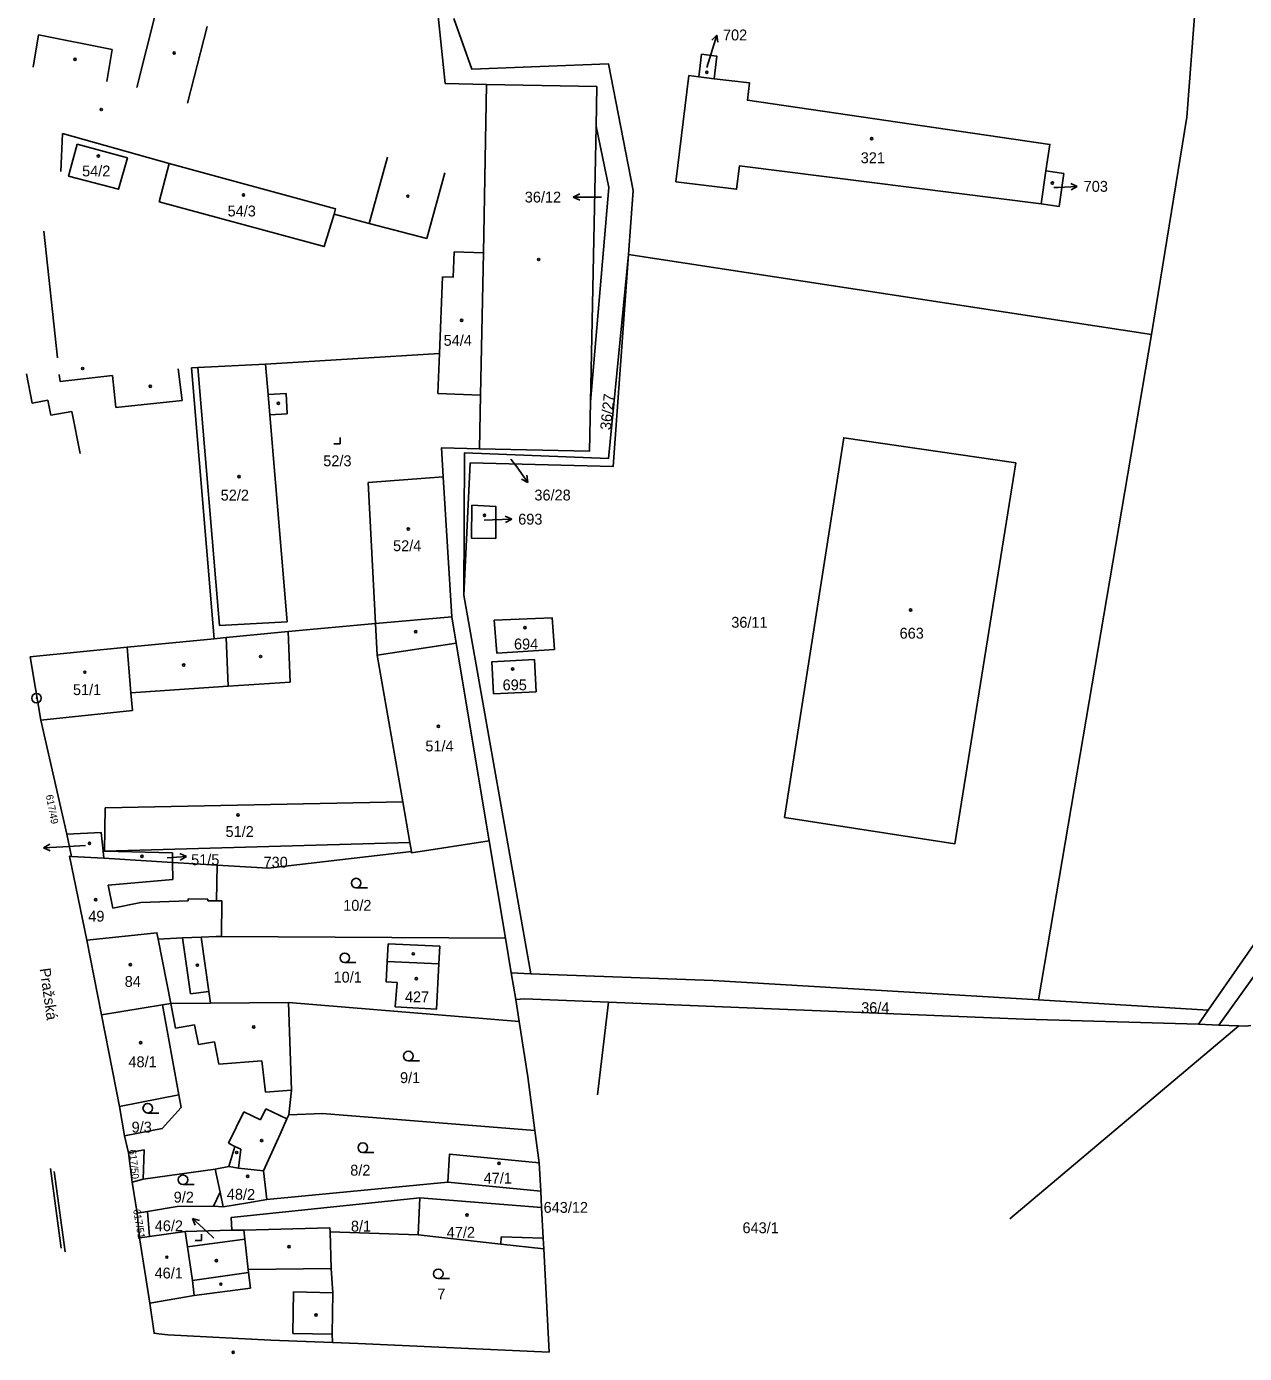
# Model space of a CAD drawing. Extents: x -783948 to -781889, y -1005870 to -1004430.
# Drawn here: x -782644.9 to -782454.1, y -1005869.8 to -1005661.9 of the extents above; entities that cross this region are included whole.
import ezdxf

# ---------------------------------------------------------------- set-up
doc = ezdxf.new("R2010")
doc.units = 0
for name, color, linetype in [('Vrstva 1', 7, 'Continuous'), ('Vrstva 2', 7, 'Continuous'), ('Vrstva 3', 7, 'Continuous'), ('Vrstva 4', 7, 'Continuous'), ('Vrstva 5', 7, 'Continuous'), ('Vrstva 7', 7, 'Continuous'), ('Vrstva 8', 7, 'Continuous')]:
    doc.layers.add(name, color=color, linetype=linetype)

msp = doc.modelspace()

# ---------------------------------------------------------------- linework, layer by layer
at = {"layer": 'Vrstva 1'}
for p, q in [((-782580.46, -1005660.33), (-782579.32, -1005670.89)), ((-782537.2, -1005670.12), (-782539.61, -1005669.83)), ((-782572.84, -1005671.02), (-782579.32, -1005670.89)), ((-782555.58, -1005671.36), (-782572.84, -1005671.02)), ((-782555.71, -1005677.54), (-782555.58, -1005671.36)), ((-782556.59, -1005720.71), (-782555.71, -1005677.54)), ((-782486, -1005689.74), (-782485.24, -1005684.56)), ((-782485.24, -1005684.56), (-782482.42, -1005684.99)), ((-782482.42, -1005684.99), (-782483.18, -1005690.13)), ((-782483.18, -1005690.13), (-782486, -1005689.74)), ((-782550.6, -1005697.65), (-782468.7, -1005710.19)), ((-782580.24, -1005713.13), (-782579.78, -1005701.14)), ((-782468.7, -1005710.19), (-782486.38, -1005814.37)), ((-782580.24, -1005713.13), (-782607.48, -1005714.81)), ((-782618.07, -1005715.37), (-782619.07, -1005715.42)), ((-782615.5, -1005757.82), (-782619.07, -1005715.42)), ((-782607.48, -1005714.81), (-782618.07, -1005715.37)), ((-782618.07, -1005715.37), (-782614.7, -1005755.73)), ((-782604.11, -1005722.61), (-782604.25, -1005719.42)), ((-782573.95, -1005728.07), (-782573.79, -1005719.66)), ((-782578.29, -1005754.37), (-782579.65, -1005732.46)), ((-782576.39, -1005750.98), (-782565.92, -1005810.3)), ((-782614.7, -1005755.73), (-782604.09, -1005755.19)), ((-782578.29, -1005754.37), (-782590.23, -1005755.45)), ((-782632.69, -1005791.09), (-782632.59, -1005784.29)), ((-782632.59, -1005784.29), (-782585.99, -1005783.36)), ((-782584.88, -1005789.75), (-782585.99, -1005783.36)), ((-782637.85, -1005791.91), (-782638.59, -1005788.42)), ((-782632.69, -1005791.09), (-782584.88, -1005789.75)), ((-782584.88, -1005789.75), (-782584.63, -1005791.16)), ((-782569.89, -1005804.73), (-782572.45, -1005789.49)), ((-782632.78, -1005792.21), (-782637.85, -1005791.91)), ((-782632.9, -1005791.09), (-782632.69, -1005791.09)), ((-782632.9, -1005791.09), (-782632.78, -1005792.21)), ((-782622.03, -1005792.86), (-782632.78, -1005792.21)), ((-782622.05, -1005791.33), (-782632.69, -1005791.09)), ((-782622.03, -1005792.86), (-782622.05, -1005791.33)), ((-782615.07, -1005793.28), (-782622.03, -1005792.86)), ((-782635.48, -1005805.01), (-782633.18, -1005816.7)), ((-782569.89, -1005804.73), (-782614.39, -1005804.47)), ((-782568.98, -1005810.16), (-782569.89, -1005804.73)), ((-782565.92, -1005810.3), (-782568.98, -1005810.16)), ((-782568.28, -1005814.33), (-782568.98, -1005810.16)), ((-782603.87, -1005814.79), (-782616.1, -1005814.88)), ((-782567.74, -1005817.79), (-782603.87, -1005814.79)), ((-782567.74, -1005817.79), (-782568.28, -1005814.33)), ((-782553.75, -1005814.74), (-782555.46, -1005829.27)), ((-782486.38, -1005814.37), (-782459.82, -1005815.99)), ((-782633.18, -1005816.7), (-782630.36, -1005831.08)), ((-782461.32, -1005818.2), (-782459.82, -1005815.99)), ((-782490.91, -1005848.68), (-782455.01, -1005818.44)), ((-782458.16, -1005818.32), (-782461.32, -1005818.2)), ((-782455.01, -1005818.44), (-782458.16, -1005818.32)), ((-782630.36, -1005831.08), (-782629.54, -1005835.68)), ((-782598.54, -1005832.18), (-782603.85, -1005832.37)), ((-782565.28, -1005834.82), (-782598.54, -1005832.18)), ((-782629.54, -1005835.68), (-782628.92, -1005838.35)), ((-782564.61, -1005839.9), (-782565.28, -1005834.82)), ((-782628.34, -1005842.92), (-782628.92, -1005838.35)), ((-782626.64, -1005842.48), (-782628.34, -1005842.92)), ((-782626.64, -1005842.48), (-782615.37, -1005840.91)), ((-782615.37, -1005840.91), (-782614.59, -1005844.5)), ((-782607.26, -1005845.66), (-782607.8, -1005841.15)), ((-782628.34, -1005842.92), (-782627.59, -1005847.8)), ((-782614.59, -1005844.5), (-782615.63, -1005846.67)), ((-782614.09, -1005846.78), (-782615.63, -1005846.67)), ((-782583.33, -1005845.38), (-782583.57, -1005851.18)), ((-782583.33, -1005845.38), (-782564.24, -1005846.87)), ((-782627.59, -1005847.8), (-782625.95, -1005847.52)), ((-782627.21, -1005851.66), (-782627.59, -1005847.8)), ((-782625.95, -1005847.52), (-782625.66, -1005851.44)), ((-782620.05, -1005850.63), (-782625.66, -1005851.44)), ((-782612.74, -1005850.46), (-782620.05, -1005850.63)), ((-782610.87, -1005850.42), (-782612.74, -1005850.46)), ((-782583.57, -1005851.18), (-782597.37, -1005850.7)), ((-782625.66, -1005851.44), (-782627.21, -1005851.66)), ((-782563.03, -1005869.55), (-782563.89, -1005853.39)), ((-782597, -1005868.03), (-782606.64, -1005867.68)), ((-782592.99, -1005868.18), (-782597, -1005868.03)), ((-782563.03, -1005869.55), (-782592.99, -1005868.18))]:
    msp.add_line(p, q, dxfattribs=at)
for points in [[(-782459.82, -1005815.99), (-782443.68, -1005792.79), (-782417.66, -1005746.96), (-782388.6, -1005683.51), (-782362.9, -1005633.05), (-782362.27, -1005590.2)], [(-782359.84, -1005633.71), (-782386.44, -1005686.23), (-782414.15, -1005746.16), (-782437.86, -1005788.34), (-782449.27, -1005805.98), (-782458.16, -1005818.32)], [(-782461.42, -1005652.75), (-782463.16, -1005676.14), (-782468.7, -1005710.19)], [(-782577.99, -1005660.71), (-782575.15, -1005668.63), (-782553.77, -1005667.77), (-782549.87, -1005687.65), (-782550.6, -1005697.65)], [(-782539.61, -1005669.83), (-782539.18, -1005666.3), (-782536.78, -1005666.59), (-782537.2, -1005670.12)], [(-782539.61, -1005669.83), (-782541.16, -1005669.64), (-782543.19, -1005686.26), (-782533.69, -1005687.42), (-782533.25, -1005683.79), (-782486, -1005689.74)], [(-782485.24, -1005684.56), (-782484.62, -1005680.4), (-782532, -1005673.5), (-782531.67, -1005670.79), (-782537.2, -1005670.12)], [(-782556.59, -1005720.71), (-782553.71, -1005687.16), (-782555.71, -1005677.54)], [(-782637, -1005680.39), (-782629.1, -1005682.52), (-782630.48, -1005687.43), (-782638.33, -1005685.39), (-782637, -1005680.39)], [(-782624.14, -1005689.38), (-782622.56, -1005683.38), (-782596.51, -1005690.51), (-782596.73, -1005691.33), (-782598.27, -1005696.4), (-782624.14, -1005689.38)], [(-782579.78, -1005701.14), (-782578.09, -1005701.2), (-782577.93, -1005697.21)], [(-782577.93, -1005697.21), (-782573.35, -1005697.38), (-782573.79, -1005719.66)], [(-782550.6, -1005697.65), (-782553, -1005730.83), (-782575.4, -1005730.29), (-782576.39, -1005750.98)], [(-782576.39, -1005750.98), (-782576.29, -1005728.69), (-782553.76, -1005729.62), (-782550.6, -1005697.65)], [(-782573.79, -1005719.66), (-782580.48, -1005719.41), (-782580.24, -1005713.13)], [(-782604.25, -1005719.42), (-782607.08, -1005719.56), (-782607.48, -1005714.81)], [(-782573.95, -1005728.07), (-782556.75, -1005728.46), (-782556.59, -1005720.71)], [(-782604.09, -1005755.19), (-782606.81, -1005722.78), (-782604.11, -1005722.61)], [(-782526.19, -1005785.84), (-782516.92, -1005726.34), (-782489.96, -1005730.3), (-782499.49, -1005789.92), (-782526.19, -1005785.84)], [(-782579.65, -1005732.46), (-782579.93, -1005727.93), (-782573.95, -1005728.07)], [(-782590.23, -1005755.45), (-782591.38, -1005733.37), (-782579.65, -1005732.46)], [(-782575.15, -1005736.91), (-782571.39, -1005737.14), (-782571.41, -1005742.11), (-782575.19, -1005742.09), (-782575.15, -1005736.91)], [(-782590.23, -1005755.45), (-782603.94, -1005756.68), (-782613.64, -1005757.64), (-782615.5, -1005757.82)], [(-782585.99, -1005783.36), (-782589.97, -1005760.42), (-782590.23, -1005755.45)], [(-782572.45, -1005789.49), (-782577.6, -1005758.52), (-782578.29, -1005754.37)], [(-782562.22, -1005759.49), (-782571.25, -1005760.08), (-782571.65, -1005754.94), (-782562.59, -1005754.53), (-782562.22, -1005759.49)], [(-782615.5, -1005757.82), (-782629.15, -1005759.15), (-782643.89, -1005760.6)], [(-782643.89, -1005760.6), (-782644.34, -1005760.66), (-782642.66, -1005770.59), (-782638.59, -1005788.42)], [(-782565.08, -1005766.14), (-782571.78, -1005766.43), (-782572.05, -1005761.46), (-782565.36, -1005761.09), (-782565.08, -1005766.14)], [(-782638.59, -1005788.42), (-782633.22, -1005788.19), (-782632.9, -1005791.09)], [(-782584.63, -1005791.16), (-782584.6, -1005791.36), (-782572.45, -1005789.49)], [(-782637.85, -1005791.91), (-782638.2, -1005791.89), (-782635.48, -1005805.01)], [(-782584.63, -1005791.16), (-782607.08, -1005793.76), (-782615.07, -1005793.28)], [(-782614.39, -1005804.47), (-782614.33, -1005798.85), (-782615.13, -1005798.86), (-782615.07, -1005793.28)], [(-782635.48, -1005805.01), (-782625.96, -1005804.04), (-782624.5, -1005803.87), (-782624.31, -1005804.85), (-782620.49, -1005804.69), (-782617.57, -1005804.57)], [(-782617.57, -1005804.57), (-782615.19, -1005804.47), (-782614.39, -1005804.47)], [(-782616.1, -1005814.88), (-782616.36, -1005813.05), (-782617.57, -1005804.57)], [(-782586.87, -1005811.68), (-782588.59, -1005811.55), (-782588.41, -1005808.36), (-782588.25, -1005805.61), (-782580.18, -1005805.97), (-782580.32, -1005808.71), (-782580.68, -1005815.81), (-782587.17, -1005815.49), (-782586.87, -1005811.68)], [(-782486.38, -1005814.37), (-782537.35, -1005811.36), (-782565.92, -1005810.3)], [(-782616.1, -1005814.88), (-782622.33, -1005814.93), (-782623.62, -1005815.14), (-782633.18, -1005816.7)], [(-782603.85, -1005832.37), (-782603.42, -1005828.52), (-782603.87, -1005814.79)], [(-782568.28, -1005814.33), (-782566.92, -1005814.21), (-782553.75, -1005814.74)], [(-782553.75, -1005814.74), (-782488.64, -1005817.38), (-782461.32, -1005818.2)], [(-782565.28, -1005834.82), (-782566.39, -1005826.44), (-782567.74, -1005817.79)], [(-782455.01, -1005818.44), (-782453.88, -1005818.48), (-782453.15, -1005818.39)], [(-782630.36, -1005831.08), (-782621.04, -1005829.25), (-782620.69, -1005831.22), (-782623.66, -1005834.53), (-782629.54, -1005835.68)], [(-782607.8, -1005841.15), (-782605.2, -1005835.41), (-782604.14, -1005833.03), (-782603.85, -1005832.37)], [(-782628.92, -1005838.35), (-782626.5, -1005837.89), (-782626.64, -1005842.48)], [(-782564.61, -1005839.9), (-782578.65, -1005838.52), (-782578.91, -1005842.91), (-782607.26, -1005845.66)], [(-782615.37, -1005840.91), (-782613.21, -1005840.46), (-782611.69, -1005840.73), (-782607.8, -1005841.15)], [(-782564.24, -1005846.87), (-782564.37, -1005844.35), (-782564.61, -1005839.9)], [(-782615.63, -1005846.67), (-782621.3, -1005846.72), (-782625.95, -1005847.52)], [(-782607.26, -1005845.66), (-782610.24, -1005846.15), (-782614.09, -1005846.78)], [(-782612.74, -1005850.46), (-782612.84, -1005848.47), (-782583.33, -1005845.38)], [(-782563.89, -1005853.39), (-782563.98, -1005851.72), (-782564.24, -1005846.87)], [(-782610.87, -1005850.42), (-782610.71, -1005851.84), (-782619.69, -1005853.08), (-782620.05, -1005850.63)], [(-782597.37, -1005850.7), (-782597.39, -1005850.1), (-782610.87, -1005850.42)], [(-782597, -1005868.03), (-782597.03, -1005866.71), (-782596.92, -1005860.25), (-782597.22, -1005856.46), (-782597.37, -1005850.7)], [(-782627.21, -1005851.66), (-782625.62, -1005861.88), (-782624.94, -1005866.58), (-782624.18, -1005866.67)], [(-782583.57, -1005851.18), (-782570.64, -1005852.63), (-782563.89, -1005853.39)], [(-782606.64, -1005867.68), (-782622.79, -1005866.83), (-782624.18, -1005866.67)]]:
    msp.add_lwpolyline(points, dxfattribs=at)
at = {"layer": 'Vrstva 3'}
for p, q in [((-782595.76, -1005727.31), (-782595.76, -1005726.31)), ((-782596.76, -1005727.31), (-782595.76, -1005727.31)), ((-782593.28, -1005796.84), (-782591.53, -1005796.84)), ((-782595.06, -1005808.55), (-782593.31, -1005808.55)), ((-782585.11, -1005823.93), (-782583.36, -1005823.93)), ((-782625.92, -1005832.1), (-782624.17, -1005832.1)), ((-782592.24, -1005838.27), (-782590.49, -1005838.27)), ((-782620.41, -1005843.3), (-782618.66, -1005843.3)), ((-782617.49, -1005852.06), (-782617.49, -1005851.06)), ((-782618.49, -1005852.06), (-782617.49, -1005852.06)), ((-782580.42, -1005858.03), (-782578.67, -1005858.03))]:
    msp.add_line(p, q, dxfattribs=at)
for centre in [(-782593.28, -1005796.09), (-782595.06, -1005807.8), (-782585.11, -1005823.18), (-782625.92, -1005831.35), (-782592.24, -1005837.52), (-782620.41, -1005842.55), (-782580.42, -1005857.28)]:
    msp.add_circle(centre, 0.75, dxfattribs=at)
at = {"layer": 'Vrstva 4'}
for p, q in [((-782627.64, -1005671.48), (-782624.58, -1005659.51)), ((-782619.68, -1005673.93), (-782616.62, -1005661.96)), ((-782643.04, -1005663.27), (-782643.86, -1005668.29)), ((-782643.04, -1005663.27), (-782631.5, -1005665.54)), ((-782631.5, -1005665.54), (-782632.33, -1005670.56)), ((-782572.84, -1005671.02), (-782573.35, -1005697.38)), ((-782639.53, -1005684.67), (-782639.3, -1005678.71)), ((-782639.3, -1005678.71), (-782622.56, -1005683.38)), ((-782591.22, -1005692.79), (-782588.38, -1005682.43)), ((-782582.23, -1005695.16), (-782579.41, -1005684.87)), ((-782596.73, -1005691.33), (-782591.22, -1005692.79)), ((-782591.22, -1005692.79), (-782582.23, -1005695.16)), ((-782642.18, -1005694.01), (-782640.08, -1005713.84)), ((-782621.17, -1005715.53), (-782620.51, -1005720.53)), ((-782644.01, -1005720.91), (-782644.91, -1005716.32)), ((-782639.81, -1005716.44), (-782639.62, -1005717.52)), ((-782639.62, -1005717.52), (-782631.46, -1005716.62)), ((-782631.46, -1005716.62), (-782630.94, -1005721.63)), ((-782607.08, -1005719.56), (-782606.81, -1005722.78)), ((-782644.01, -1005720.91), (-782641.57, -1005720.48)), ((-782641.11, -1005722.83), (-782641.57, -1005720.48)), ((-782641.11, -1005722.83), (-782637.82, -1005722.25)), ((-782636.53, -1005728.84), (-782637.82, -1005722.25)), ((-782630.94, -1005721.63), (-782620.51, -1005720.53)), ((-782603.94, -1005756.68), (-782603.61, -1005764.62)), ((-782628.56, -1005766.29), (-782629.15, -1005759.15)), ((-782613.64, -1005757.64), (-782613.32, -1005765.27)), ((-782589.97, -1005760.42), (-782577.6, -1005758.52)), ((-782613.32, -1005765.27), (-782628.56, -1005766.29)), ((-782603.61, -1005764.62), (-782613.32, -1005765.27)), ((-782628.33, -1005769.06), (-782628.56, -1005766.29)), ((-782642.66, -1005770.59), (-782628.33, -1005769.06)), ((-782622.03, -1005792.86), (-782622, -1005795.52)), ((-782622, -1005795.52), (-782632.15, -1005796.42)), ((-782632.15, -1005796.42), (-782631.4, -1005800.03)), ((-782631.4, -1005800.03), (-782626.99, -1005799.12)), ((-782626.99, -1005799.12), (-782619.6, -1005798.89)), ((-782619.6, -1005798.57), (-782616.5, -1005798.59)), ((-782619.6, -1005798.89), (-782619.6, -1005798.57)), ((-782616.5, -1005798.59), (-782616.5, -1005798.89)), ((-782616.5, -1005798.89), (-782615.13, -1005798.86)), ((-782624.31, -1005804.85), (-782622.33, -1005814.93)), ((-782620.49, -1005804.69), (-782619.24, -1005813.46)), ((-782580.32, -1005808.71), (-782588.41, -1005808.36)), ((-782619.24, -1005813.46), (-782616.36, -1005813.05)), ((-782623.62, -1005815.14), (-782621.04, -1005829.25)), ((-782622.33, -1005814.93), (-782621.57, -1005818.79)), ((-782621.57, -1005818.79), (-782618.6, -1005818.3)), ((-782618.6, -1005818.3), (-782618, -1005821.36)), ((-782618, -1005821.36), (-782615.46, -1005820.95)), ((-782615.46, -1005820.95), (-782614.77, -1005824.46)), ((-782614.77, -1005824.46), (-782608.06, -1005823.95)), ((-782608.06, -1005823.95), (-782607.49, -1005828.83)), ((-782607.49, -1005828.83), (-782603.42, -1005828.52)), ((-782613.26, -1005836.84), (-782610.88, -1005831.9)), ((-782608.24, -1005833.18), (-782610.88, -1005831.9)), ((-782608.24, -1005833.18), (-782607.41, -1005831.45)), ((-782604.14, -1005833.03), (-782607.41, -1005831.45)), ((-782612.27, -1005837.32), (-782613.26, -1005836.84)), ((-782613.21, -1005840.46), (-782612.27, -1005837.32)), ((-782611.34, -1005837.77), (-782612.27, -1005837.32)), ((-782611.69, -1005840.73), (-782611.34, -1005837.77)), ((-782639.47, -1005853.28), (-782641.16, -1005840.81)), ((-782638.88, -1005853.82), (-782640.58, -1005841.26)), ((-782614.59, -1005844.5), (-782614.09, -1005846.78)), ((-782564.37, -1005844.35), (-782578.91, -1005842.91)), ((-782618.9, -1005858.33), (-782619.69, -1005853.08)), ((-782610.71, -1005851.84), (-782610.18, -1005856.62)), ((-782570.64, -1005852.63), (-782570.59, -1005851.49)), ((-782570.59, -1005851.49), (-782563.98, -1005851.72)), ((-782610.13, -1005857.05), (-782618.9, -1005858.33)), ((-782610.18, -1005856.62), (-782597.22, -1005856.46)), ((-782610.18, -1005856.62), (-782610.13, -1005857.05)), ((-782609.85, -1005859.51), (-782610.13, -1005857.05)), ((-782618.63, -1005860.69), (-782618.9, -1005858.33)), ((-782625.62, -1005861.88), (-782618.63, -1005860.69)), ((-782618.63, -1005860.69), (-782609.85, -1005859.51)), ((-782603.19, -1005866.65), (-782603.08, -1005860.1)), ((-782603.08, -1005860.1), (-782596.92, -1005860.25)), ((-782597.03, -1005866.71), (-782603.19, -1005866.65))]:
    msp.add_line(p, q, dxfattribs=at)
at = {"layer": 'Vrstva 5'}
for centre in [(-782621.79, -1005666.08), (-782637.32, -1005667.08), (-782538.35, -1005669.13), (-782633.21, -1005674.94), (-782512.54, -1005679.52), (-782633.66, -1005682.23), (-782484.23, -1005686.47), (-782610.93, -1005688.33), (-782585.19, -1005688.51), (-782564.69, -1005698.43), (-782576.77, -1005707.95), (-782636.11, -1005715.5), (-782625.53, -1005718.29), (-782605.47, -1005720.96), (-782611.62, -1005732.43), (-782573.18, -1005738.48), (-782585.12, -1005740.64), (-782506.44, -1005753.31), (-782583.96, -1005756.71), (-782566.85, -1005756.08), (-782608.25, -1005760.61), (-782635.78, -1005763.06), (-782620.29, -1005761.94), (-782568.77, -1005762.56), (-782580.4, -1005771.53), (-782611.79, -1005785.41), (-782635.05, -1005789.85), (-782626.82, -1005791.91), (-782634.08, -1005798.7), (-782584.33, -1005807.17), (-782628.65, -1005808.87), (-782618.14, -1005808.95), (-782583.85, -1005811.06), (-782609.32, -1005818.62), (-782627.04, -1005821.09), (-782608.08, -1005836.41), (-782611.99, -1005838.28), (-782570.91, -1005839.98), (-782610.27, -1005842.03), (-782575.91, -1005848.08), (-782603.79, -1005853.04), (-782622.93, -1005854.68), (-782615.17, -1005855.24), (-782614.48, -1005858.9), (-782599.56, -1005863.74), (-782612.55, -1005869.58)]:
    msp.add_circle(centre, 0.175, dxfattribs=at)
at = {"layer": 'Vrstva 7'}
for p, q in [((-782537.68, -1005666.15), (-782536.8, -1005663.28)), ((-782536.8, -1005663.28), (-782537.57, -1005664.09)), ((-782536.8, -1005663.28), (-782536.62, -1005664.38)), ((-782538.34, -1005668.36), (-782537.68, -1005666.15)), ((-782480.33, -1005686.98), (-782481.36, -1005686.54)), ((-782559.27, -1005688.66), (-782558.27, -1005688.16)), ((-782556.27, -1005688.66), (-782559.27, -1005688.66)), ((-782559.27, -1005688.66), (-782558.27, -1005689.16)), ((-782556.27, -1005688.66), (-782554.84, -1005688.66)), ((-782484.02, -1005687.18), (-782483.33, -1005687.14)), ((-782483.33, -1005687.14), (-782480.33, -1005686.98)), ((-782480.33, -1005686.98), (-782481.31, -1005687.54)), ((-782569.05, -1005729.68), (-782568.14, -1005730.91)), ((-782568.14, -1005730.91), (-782566.38, -1005733.34)), ((-782566.38, -1005733.34), (-782566.56, -1005732.23)), ((-782566.38, -1005733.34), (-782567.37, -1005732.82)), ((-782568.9, -1005739.09), (-782569.92, -1005738.63)), ((-782573.25, -1005739.25), (-782571.9, -1005739.2)), ((-782571.9, -1005739.2), (-782568.9, -1005739.09)), ((-782568.9, -1005739.09), (-782569.88, -1005739.63)), ((-782642.24, -1005790.57), (-782641.26, -1005790.02)), ((-782639.24, -1005790.41), (-782642.24, -1005790.57)), ((-782642.24, -1005790.57), (-782641.21, -1005791.02)), ((-782635.65, -1005790.2), (-782639.24, -1005790.41)), ((-782622.87, -1005792.12), (-782619.88, -1005791.91)), ((-782619.88, -1005791.91), (-782620.91, -1005791.48)), ((-782619.88, -1005791.91), (-782620.84, -1005792.48)), ((-782616.69, -1005850.65), (-782618.89, -1005848.6)), ((-782618.89, -1005848.6), (-782617.81, -1005848.92)), ((-782618.89, -1005848.6), (-782618.49, -1005849.65)), ((-782615.58, -1005851.68), (-782616.69, -1005850.65))]:
    msp.add_line(p, q, dxfattribs=at)
at = {"layer": 'Vrstva 8'}
for radius in [0.75, 0.03]:
    msp.add_circle((-782643.35, -1005767.13), radius, dxfattribs=at)

# ---------------------------------------------------------------- texts
at = {"layer": 'Vrstva 2'}
for s, p in [('702', (-782535.83, -1005664.12)), ('321', (-782514.25, -1005683.35)), ('54/2', (-782636.21, -1005685.42)), ('703', (-782479.33, -1005687.83)), ('36/12', (-782566.87, -1005689.51)), ('54/3', (-782613.42, -1005691.69)), ('54/4', (-782579.58, -1005711.95)), ('52/3', (-782598.43, -1005730.81)), ('52/2', (-782614.5, -1005736.19)), ('36/28', (-782565.36, -1005736.17)), ('693', (-782567.9, -1005739.95)), ('52/4', (-782587.5, -1005744.11)), ('36/11', (-782534.53, -1005756.1)), ('663', (-782508.16, -1005757.81)), ('694', (-782568.56, -1005759.5)), ('51/1', (-782637.64, -1005766.65)), ('695', (-782570.34, -1005765.9)), ('51/4', (-782582.44, -1005775.47)), ('51/2', (-782613.74, -1005788.87)), ('51/5', (-782619.13, -1005793.28)), ('730', (-782607.79, -1005793.67)), ('10/2', (-782595.31, -1005800.43)), ('49', (-782635.24, -1005802.13)), ('84', (-782629.53, -1005812.34)), ('10/1', (-782596.82, -1005811.67)), ('427', (-782585.64, -1005814.76)), ('36/4', (-782514.18, -1005816.45)), ('48/1', (-782628.95, -1005824.93)), ('9/1', (-782586.41, -1005827.41)), ('9/3', (-782628.45, -1005835.16)), ('8/2', (-782594.21, -1005841.9)), ('47/1', (-782573.31, -1005843.14)), ('9/2', (-782621.86, -1005846.12)), ('643/12', (-782563.92, -1005847.73)), ('46/2', (-782624.83, -1005850.61)), ('8/1', (-782594.1, -1005850.66)), ('47/2', (-782579.09, -1005851.63)), ('643/1', (-782532.77, -1005850.92)), ('46/1', (-782624.85, -1005858.01)), ('7', (-782580.58, -1005861.3))]:
    msp.add_text(s, height=1.7, dxfattribs=at).set_placement(p)
for s, height, rotation, p in [('36/27', 1.7, 84, (-782553.39, -1005725.2)), ('617/49', 1.139, 281, (-782641.9, -1005782.35)), ('617/50', 1.139, 276, (-782628.88, -1005837.85)), ('48/2', 1.7, 359, (-782613.55, -1005845.64)), ('617/51', 1.139, 280, (-782628.22, -1005847.25))]:
    msp.add_text(s, height=height, rotation=rotation, dxfattribs=at).set_placement(p)
at = {"layer": 'Vrstva 7'}
msp.add_text('Pražská', height=1.7, rotation=278, dxfattribs=at).set_placement((-782642.86, -1005809.51))

doc.saveas('drawing.dxf')
